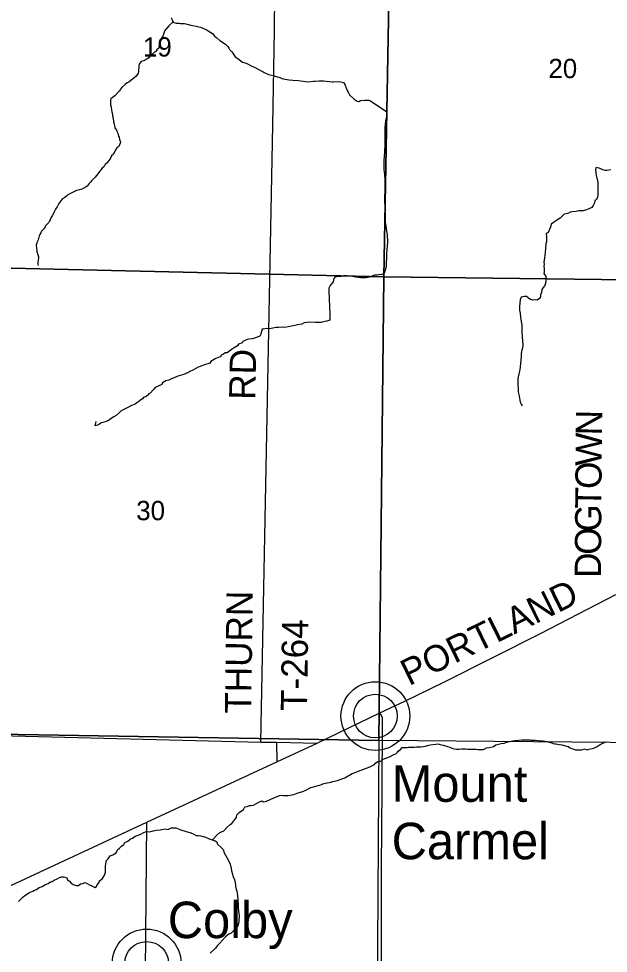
# Model space of a CAD drawing. Extents: x 0 to 34, y 0 to 22.
# Drawn here: x 3.375 to 4.651, y 14.74 to 16.762 of the extents above; entities that cross this region are included whole.
import ezdxf

# ---------------------------------------------------------------- set-up
doc = ezdxf.new("R2010")
doc.units = 0
for name, color, linetype in [('GM_X_County_Road', 7, 'Continuous'), ('GM_X_County_Road_Text', 7, 'Continuous'), ('GM_X_Minor_River', 7, 'Continuous'), ('GM_X_Section', 7, 'Continuous'), ('GM_X_Section_Text', 7, 'Continuous'), ('GM_X_Township_Road', 7, 'Continuous'), ('GM_X_Township_Road_Text', 7, 'Continuous'), ('GM_X_Unincorporated', 7, 'Continuous'), ('GM_X_Unincorporated_Location', 7, 'Continuous'), ('GM_X_Unincorporated_Text', 7, 'Continuous')]:
    doc.layers.add(name, color=color, linetype=linetype)

msp = doc.modelspace()

# ---------------------------------------------------------------- linework, layer by layer
at = {"layer": 'GM_X_County_Road'}
msp.add_lwpolyline([(3.1578, 14.7935), (3.6526, 15.0232), (3.9337, 15.154), (4.0209, 15.1945), (4.1568, 15.2599), (4.2108, 15.2852), (4.2951, 15.3262), (4.5042, 15.4319), (4.6673, 15.5158)], dxfattribs=at)
at = {"layer": 'GM_X_Minor_River'}
for points in [[(3.7106, 16.7555), (3.7092, 16.7553), (3.7, 16.7468), (3.6955, 16.7418), (3.6917, 16.7361), (3.6898, 16.7327), (3.6876, 16.7258), (3.685, 16.7213), (3.6831, 16.716), (3.6823, 16.7133), (3.6812, 16.7099), (3.6805, 16.7053), (3.6786, 16.7015), (3.6782, 16.6985), (3.6741, 16.6943), (3.6718, 16.6912), (3.6692, 16.6897), (3.6654, 16.6859), (3.6605, 16.6828), (3.6571, 16.6775), (3.6533, 16.6752), (3.6488, 16.6721), (3.6457, 16.671)], [(3.7056, 16.7635), (3.7068, 16.7605), (3.7095, 16.7548), (3.7133, 16.7529), (3.7159, 16.7526), (3.7186, 16.7526), (3.7224, 16.7522), (3.7254, 16.7519), (3.7307, 16.7515), (3.7342, 16.7515), (3.7395, 16.75), (3.7475, 16.7482), (3.7589, 16.7459), (3.7649, 16.7445), (3.7687, 16.7433), (3.7805, 16.7388), (3.7832, 16.7369), (3.7908, 16.732), (3.7946, 16.7302), (3.7996, 16.7237), (3.8041, 16.7207), (3.8106, 16.7147), (3.816, 16.7113), (3.8232, 16.706), (3.8274, 16.7018), (3.8301, 16.698), (3.8316, 16.6954), (3.8362, 16.6901)], [(3.8362, 16.6901), (3.8389, 16.6874), (3.8438, 16.6791), (3.8492, 16.6757), (3.8598, 16.6682), (3.8674, 16.6655), (3.8701, 16.664), (3.88, 16.6592), (3.8857, 16.6573), (3.8903, 16.6543), (3.8937, 16.6524), (3.8983, 16.6497), (3.9017, 16.6482), (3.9066, 16.6452), (3.9127, 16.643), (3.9158, 16.6415), (3.9196, 16.6403), (3.926, 16.6389), (3.9348, 16.6362), (3.9378, 16.6351), (3.9473, 16.6317), (3.9564, 16.6306), (3.9606, 16.6299), (3.9686, 16.6292), (3.9804, 16.6285), (3.9853, 16.6277), (3.9959, 16.6263), (4.002, 16.6255), (4.0134, 16.6267), (4.0161, 16.6271), (4.0255, 16.6276), (4.035, 16.6276), (4.0403, 16.6269), (4.0479, 16.6261), (4.0533, 16.6254), (4.0563, 16.6254), (4.0677, 16.6262), (4.0719, 16.6255), (4.0783, 16.6236), (4.0814, 16.6179), (4.0837, 16.6123), (4.0864, 16.6054), (4.0887, 16.6013), (4.0906, 16.5971), (4.1009, 16.5877), (4.1074, 16.5835), (4.1108, 16.5831), (4.115, 16.5847), (4.1244, 16.5859), (4.1286, 16.5859), (4.1324, 16.5855), (4.1351, 16.5852), (4.1709, 16.561), (4.1709, 16.5504), (4.1698, 16.5447), (4.1691, 16.5394), (4.1683, 16.5352), (4.1673, 16.5242), (4.1673, 16.5215), (4.1677, 16.5181), (4.1673, 16.5074), (4.1674, 16.4911), (4.1671, 16.4843), (4.1667, 16.4793), (4.1664, 16.4748), (4.1664, 16.4706), (4.166, 16.4668), (4.1661, 16.463), (4.1653, 16.4573), (4.1654, 16.4451), (4.165, 16.4398), (4.1654, 16.436), (4.1662, 16.4296), (4.1666, 16.4258), (4.1667, 16.4197), (4.167, 16.4166), (4.1671, 16.414), (4.1671, 16.3996), (4.1675, 16.3961), (4.1672, 16.3912), (4.1672, 16.3882), (4.1669, 16.3779), (4.1669, 16.3718), (4.1666, 16.3631), (4.167, 16.3597), (4.167, 16.3498), (4.1674, 16.3437), (4.1678, 16.3392), (4.1679, 16.3274), (4.1683, 16.3209), (4.1687, 16.3175), (4.1699, 16.3092), (4.171, 16.3023), (4.1714, 16.2989), (4.1722, 16.294), (4.1722, 16.2906), (4.173, 16.2826), (4.1731, 16.2761), (4.1727, 16.2716), (4.172, 16.2605), (4.1713, 16.256)], [(3.6457, 16.671), (3.6427, 16.6702), (3.6393, 16.6683), (3.6363, 16.6637), (3.6355, 16.6599), (3.6352, 16.6568), (3.6348, 16.6504), (3.6348, 16.647), (3.6341, 16.6439), (3.6296, 16.6378), (3.6247, 16.6332), (3.6182, 16.6283), (3.6137, 16.6248), (3.6103, 16.6229), (3.6054, 16.6199), (3.5986, 16.6134), (3.5952, 16.6088), (3.5944, 16.6061), (3.5918, 16.6042), (3.5831, 16.5951), (3.5748, 16.5889), (3.574, 16.5859), (3.5741, 16.5756), (3.5753, 16.5703), (3.5764, 16.5646), (3.5768, 16.5601), (3.578, 16.5551), (3.5784, 16.5517), (3.5799, 16.5464), (3.5807, 16.5388), (3.5819, 16.5343), (3.5834, 16.5259), (3.5869, 16.521), (3.5873, 16.5183), (3.5896, 16.5142), (3.5915, 16.5081), (3.5927, 16.5055), (3.5934, 16.5009), (3.5946, 16.4971), (3.5954, 16.4941), (3.592, 16.4857), (3.5878, 16.4823), (3.5841, 16.4765), (3.5803, 16.4686), (3.5762, 16.4651), (3.5747, 16.4617), (3.5728, 16.4583), (3.566, 16.4491), (3.5622, 16.4464), (3.56, 16.4422), (3.5562, 16.4388), (3.5528, 16.4346), (3.5501, 16.4312), (3.5467, 16.4266), (3.5437, 16.4224), (3.5407, 16.4194), (3.5366, 16.4148), (3.5332, 16.4113), (3.5317, 16.4087), (3.5279, 16.4052), (3.5237, 16.3995), (3.5211, 16.3984), (3.515, 16.3945), (3.5116, 16.3934), (3.5067, 16.3915), (3.5002, 16.3899), (3.4946, 16.3872), (3.4862, 16.383), (3.4813, 16.3811), (3.4798, 16.3784), (3.4749, 16.3754), (3.4688, 16.3708), (3.4662, 16.3677), (3.462, 16.3624), (3.4587, 16.3548), (3.4549, 16.3498), (3.453, 16.3452), (3.4515, 16.3422), (3.4481, 16.3357), (3.4451, 16.3312), (3.4432, 16.327), (3.4417, 16.3243), (3.4395, 16.3205), (3.4372, 16.3171), (3.4334, 16.3136), (3.4319, 16.3094), (3.4274, 16.3052), (3.4248, 16.3022), (3.4229, 16.2984), (3.421, 16.2953), (3.4195, 16.2923), (3.4173, 16.2835), (3.415, 16.2793), (3.4146, 16.2763), (3.4135, 16.2717), (3.4136, 16.2657), (3.4143, 16.2611), (3.4147, 16.2577), (3.417, 16.2516), (3.4182, 16.2467), (3.4182, 16.244)], [(4.6559, 16.4346), (4.6479, 16.4338), (4.6437, 16.4337), (4.6388, 16.4349), (4.6308, 16.4382), (4.6243, 16.4401), (4.6232, 16.4352), (4.6236, 16.4283), (4.6248, 16.4234), (4.6279, 16.4082), (4.6283, 16.4033), (4.6284, 16.3805), (4.6277, 16.3759), (4.6251, 16.371), (4.6213, 16.3675), (4.6209, 16.3637), (4.6179, 16.358), (4.6153, 16.3535), (4.6073, 16.35), (4.6035, 16.3485), (4.5963, 16.3465), (4.591, 16.3465), (4.5868, 16.3461), (4.5815, 16.3446), (4.5724, 16.3438), (4.5679, 16.343), (4.563, 16.3407), (4.5554, 16.3387), (4.5463, 16.3303), (4.541, 16.3265), (4.5365, 16.3242), (4.5323, 16.3208), (4.5274, 16.3173), (4.5255, 16.3112), (4.5207, 16.2994), (4.5165, 16.2968), (4.5173, 16.2895), (4.5173, 16.2831), (4.517, 16.2793), (4.5158, 16.2755), (4.5155, 16.2717), (4.5151, 16.2656), (4.514, 16.2557), (4.5126, 16.2447), (4.5115, 16.2352), (4.5119, 16.2306), (4.5115, 16.2268), (4.5119, 16.2204), (4.512, 16.2143), (4.5116, 16.2105), (4.5151, 16.2052), (4.5162, 16.2014), (4.5159, 16.1965), (4.5155, 16.1923), (4.5136, 16.1843), (4.5099, 16.1805), (4.5068, 16.1763), (4.5069, 16.1721), (4.5054, 16.1683), (4.5039, 16.1641), (4.5043, 16.1603), (4.502, 16.1565), (4.4967, 16.1531), (4.4929, 16.1534), (4.4876, 16.153), (4.4811, 16.1549), (4.4735, 16.1606)], [(3.4182, 16.244), (3.4175, 16.2391), (3.4171, 16.2349), (3.4168, 16.2311), (3.4172, 16.2277)], [(4.1713, 16.256), (4.1713, 16.2533), (4.1709, 16.2465), (4.1706, 16.2423), (4.1702, 16.2351), (4.1702, 16.2321), (4.1699, 16.2271), (4.1692, 16.2218), (4.1684, 16.2176), (4.1669, 16.2138), (4.1662, 16.2104), (4.1609, 16.2085), (4.1537, 16.2077), (4.1506, 16.2073), (4.1453, 16.2072), (4.1336, 16.203), (4.1309, 16.2022), (4.1264, 16.2015), (4.1146, 16.2014), (4.1036, 16.2025), (4.0952, 16.2047), (4.085, 16.2058), (4.0781, 16.2054), (4.0732, 16.2042), (4.0698, 16.2038), (4.0664, 16.2038), (4.0633, 16.2034), (4.0592, 16.203), (4.0569, 16.1996), (4.0558, 16.1928), (4.049, 16.1847), (4.0464, 16.1787), (4.0461, 16.1695), (4.0469, 16.1589), (4.0469, 16.1494), (4.0477, 16.1449), (4.0477, 16.1361), (4.0482, 16.1251), (4.0486, 16.1205), (4.0486, 16.1167), (4.0482, 16.1137), (4.0483, 16.1099), (4.0418, 16.1076), (4.0384, 16.1064), (4.0293, 16.1049), (4.0175, 16.1048), (4.0042, 16.1051), (3.9929, 16.1036), (3.9879, 16.1013), (3.9785, 16.0993), (3.9758, 16.0985), (3.9663, 16.0966), (3.958, 16.095), (3.9504, 16.0939), (3.9451, 16.0942), (3.9375, 16.0938), (3.9322, 16.0934), (3.9284, 16.093), (3.925, 16.0922), (3.9216, 16.0918), (3.9182, 16.0911), (3.9155, 16.091), (3.9117, 16.0914), (3.9049, 16.0898), (3.9022, 16.0898), (3.8992, 16.0803), (3.8985, 16.0769), (3.8955, 16.0742), (3.8856, 16.0708), (3.8803, 16.0692), (3.8735, 16.0684), (3.8697, 16.068), (3.8602, 16.0638), (3.8587, 16.0608), (3.8511, 16.0577), (3.8485, 16.0543), (3.8417, 16.0497), (3.8375, 16.0474), (3.8266, 16.0393), (3.822, 16.0386), (3.8186, 16.0363), (3.8133, 16.0336), (3.8118, 16.0305), (3.8069, 16.029), (3.8004, 16.0259), (3.791, 16.0205), (3.7891, 16.0164), (3.7751, 16.0125), (3.7717, 16.0106), (3.7656, 16.0087), (3.7622, 16.0075), (3.7523, 16.0014), (3.7459, 15.9983), (3.7414, 15.996), (3.7372, 15.9941), (3.7345, 15.9926), (3.7198, 15.9883), (3.7118, 15.9848), (3.7088, 15.9841), (3.7001, 15.9798), (3.6936, 15.9783)], [(4.4735, 16.1606), (4.4697, 16.1605), (4.4625, 16.1594), (4.4603, 16.1533), (4.4584, 16.1396), (4.4589, 16.1312), (4.46, 16.1248), (4.4608, 16.1157), (4.4616, 16.1111), (4.4636, 16.0986), (4.4637, 16.0838), (4.4645, 16.0739), (4.4661, 16.0553), (4.465, 16.0492), (4.4635, 16.0447), (4.4624, 16.0374), (4.462, 16.0306), (4.4595, 16.0025), (4.4569, 15.9933), (4.4551, 15.9835), (4.4551, 15.977), (4.4556, 15.9553), (4.4567, 15.9508), (4.4579, 15.9455), (4.4587, 15.9409), (4.4602, 15.9322), (4.4622, 15.928), (4.4645, 15.9242)], [(3.6936, 15.9783), (3.6864, 15.9741), (3.6849, 15.9707), (3.6705, 15.9638), (3.6671, 15.9596), (3.6596, 15.9519), (3.6569, 15.9504), (3.6547, 15.9473), (3.6501, 15.9439), (3.646, 15.9427), (3.6429, 15.9397), (3.6399, 15.937), (3.6343, 15.9328), (3.6316, 15.9317), (3.6274, 15.9278), (3.6191, 15.9251), (3.6127, 15.9217), (3.604, 15.9167), (3.5972, 15.9133), (3.5934, 15.9098), (3.5862, 15.9033), (3.5809, 15.9006), (3.5775, 15.8983), (3.5748, 15.8964), (3.5718, 15.8941), (3.568, 15.8915), (3.5623, 15.8895), (3.5574, 15.888), (3.5536, 15.8876), (3.5498, 15.8845), (3.5461, 15.8826), (3.5411, 15.8807), (3.543, 15.8902)], [(3.7942, 14.9848), (3.796, 14.9866), (3.8036, 14.9953), (3.8105, 15.0013), (3.8189, 15.0047), (3.8262, 15.0126), (3.833, 15.0182), (3.8361, 15.0208), (3.843, 15.0295), (3.8464, 15.0336), (3.8469, 15.039), (3.8522, 15.0446), (3.8614, 15.0506), (3.8645, 15.0563), (3.8698, 15.0574), (3.8747, 15.0596), (3.8778, 15.0596), (3.8831, 15.0603), (3.8937, 15.0659), (3.901, 15.0692), (3.9051, 15.0677), (3.9085, 15.068), (3.9112, 15.0688), (3.9207, 15.0732), (3.9306, 15.0773), (3.9394, 15.081), (3.9428, 15.0818), (3.9473, 15.0814), (3.9504, 15.081), (3.9542, 15.0809), (3.9583, 15.0813), (3.9705, 15.0834), (3.9777, 15.0864), (3.9823, 15.0875), (3.9899, 15.0897), (3.9967, 15.0923), (4.0074, 15.0983), (4.0131, 15.1001), (4.0184, 15.1016), (4.0234, 15.1027), (4.0268, 15.1034), (4.0302, 15.1049), (4.0332, 15.106), (4.0363, 15.1072), (4.0389, 15.1079), (4.0427, 15.1086), (4.0473, 15.109), (4.0507, 15.1101), (4.0549, 15.1112), (4.0648, 15.1137), (4.0705, 15.1156), (4.0747, 15.1171), (4.0808, 15.1193), (4.0964, 15.1286), (4.1032, 15.1309), (4.1135, 15.1353), (4.1181, 15.1368), (4.1268, 15.1405), (4.1299, 15.1409), (4.1375, 15.1446), (4.1447, 15.1483), (4.1474, 15.151), (4.1523, 15.1547), (4.1577, 15.1551), (4.1607, 15.1569), (4.1638, 15.1596), (4.1771, 15.1651), (4.187, 15.1696), (4.1915, 15.1711), (4.1946, 15.1745), (4.1965, 15.1771), (4.2011, 15.1805), (4.2049, 15.1846), (4.2118, 15.1853), (4.2159, 15.1853), (4.2186, 15.1857), (4.2231, 15.1856), (4.2315, 15.1859), (4.236, 15.1863), (4.2429, 15.1862), (4.2455, 15.1866), (4.255, 15.188), (4.26, 15.1891), (4.2657, 15.1906), (4.2778, 15.1923), (4.282, 15.1927), (4.2846, 15.1923), (4.2873, 15.1915), (4.2933, 15.1903), (4.3032, 15.1872), (4.3077, 15.186), (4.3111, 15.1845), (4.3141, 15.1829), (4.3225, 15.1813), (4.3285, 15.1813), (4.3335, 15.182), (4.3418, 15.1819), (4.3464, 15.1815), (4.3498, 15.1815), (4.36, 15.1817), (4.3642, 15.1817)], [(4.3642, 15.1817), (4.3687, 15.1809), (4.3733, 15.1805), (4.3767, 15.1805), (4.3809, 15.1808), (4.3873, 15.1842), (4.3927, 15.1853), (4.3995, 15.1863), (4.4021, 15.1871), (4.4075, 15.1908), (4.4189, 15.1934), (4.4253, 15.1945), (4.4333, 15.197), (4.4367, 15.1978), (4.4436, 15.1992), (4.4485, 15.2), (4.4546, 15.2003), (4.4573, 15.2006), (4.4637, 15.2017), (4.4701, 15.2013), (4.4808, 15.2012), (4.4834, 15.2008), (4.4925, 15.2007), (4.4993, 15.2003), (4.5096, 15.1994), (4.5183, 15.1978), (4.5228, 15.1963), (4.5258, 15.1955), (4.5285, 15.1947), (4.5315, 15.1935), (4.5349, 15.1931), (4.5376, 15.1927), (4.5448, 15.1911), (4.5501, 15.1907), (4.5607, 15.1876), (4.5637, 15.1868), (4.5671, 15.1849), (4.5697, 15.1837), (4.5735, 15.1821), (4.5762, 15.1814), (4.58, 15.1802), (4.5837, 15.1798), (4.5868, 15.1801), (4.5925, 15.1801), (4.5959, 15.1808), (4.5993, 15.1819), (4.6031, 15.1804), (4.6057, 15.1796), (4.6084, 15.1811), (4.6168, 15.1829), (4.6209, 15.1844), (4.627, 15.1874), (4.6328, 15.1911), (4.6377, 15.1937), (4.6438, 15.1963), (4.6465, 15.1974)], [(3.4758, 14.9041), (3.4796, 14.9026), (3.4808, 14.8988), (3.4854, 14.8958), (3.4892, 14.8913), (3.493, 14.8882), (3.4995, 14.886), (3.5044, 14.8864), (3.5089, 14.8898), (3.5135, 14.891), (3.5195, 14.8929), (3.5233, 14.8907), (3.5287, 14.8876), (3.5336, 14.8858), (3.5397, 14.882), (3.5435, 14.8839), (3.5454, 14.8877), (3.5491, 14.8927), (3.5503, 14.8965), (3.5567, 14.9018), (3.5601, 14.9076), (3.5631, 14.9148), (3.563, 14.9292), (3.5641, 14.933), (3.5656, 14.9402), (3.569, 14.9441), (3.5735, 14.9509), (3.5792, 14.9528), (3.586, 14.9567), (3.5894, 14.9635), (3.5932, 14.967), (3.5977, 14.9712), (3.6026, 14.9754), (3.6049, 14.9792), (3.6113, 14.9823), (3.6162, 14.9868), (3.6212, 14.9891), (3.6272, 14.993), (3.6314, 14.9949), (3.6397, 14.9976), (3.6446, 15.0003), (3.6511, 15.003), (3.6591, 15.0022), (3.6659, 15.0049), (3.6731, 15.0061), (3.6814, 15.0065), (3.692, 15.0092), (3.6977, 15.0077), (3.7061, 15.0112), (3.7103, 15.0108), (3.7156, 15.0112), (3.7258, 15.0071), (3.7376, 15.003), (3.7464, 15.0008), (3.7544, 14.9974), (3.7593, 14.9947), (3.7642, 14.9944), (3.7696, 14.994), (3.7741, 14.9925), (3.7779, 14.9914), (3.7874, 14.9873), (3.7935, 14.985), (3.8, 14.9832), (3.8038, 14.9809), (3.8053, 14.976), (3.8118, 14.9703), (3.8179, 14.9642), (3.8198, 14.957), (3.8256, 14.9472), (3.8302, 14.9389), (3.8329, 14.9324), (3.8352, 14.9229), (3.836, 14.9184), (3.8379, 14.9108), (3.8387, 14.9066), (3.8414, 14.9013), (3.8429, 14.8964), (3.8441, 14.8888), (3.8445, 14.885), (3.8461, 14.8785), (3.8472, 14.874), (3.848, 14.8698), (3.8488, 14.8641), (3.8496, 14.8546), (3.8504, 14.8447), (3.8504, 14.8394), (3.8509, 14.8307), (3.8516, 14.8261), (3.852, 14.8212), (3.8521, 14.817), (3.8517, 14.8132), (3.8517, 14.809), (3.851, 14.8041), (3.8491, 14.7988), (3.845, 14.7923), (3.8389, 14.7866), (3.8351, 14.7835), (3.8302, 14.7808), (3.823, 14.7755), (3.8159, 14.7682), (3.8098, 14.761)], [(3.3751, 14.852), (3.3849, 14.8615), (3.3887, 14.8649), (3.3989, 14.8711), (3.4058, 14.8741), (3.4099, 14.8761), (3.4137, 14.8776), (3.4194, 14.8822), (3.4258, 14.8845), (3.433, 14.8887), (3.4391, 14.8906), (3.444, 14.8941), (3.4478, 14.8949), (3.4523, 14.8979), (3.4584, 14.901), (3.4637, 14.904), (3.4682, 14.9052), (3.472, 14.9052), (3.4758, 14.9041)], [(3.8098, 14.761), (3.8045, 14.756), (3.8008, 14.7511), (3.7894, 14.7396)]]:
    msp.add_lwpolyline(points, dxfattribs=at)
at = {"layer": 'GM_X_Section'}
for points in [[(3.1868, 17.2222), (4.1831, 17.1984), (4.1651, 16.2036), (3.1722, 16.2262)], [(4.1831, 17.1984), (5.1818, 17.1932), (5.166, 16.1912), (4.1651, 16.2036)], [(4.1651, 16.2036), (4.1541, 15.2001), (3.1571, 15.217), (3.1722, 16.2262)], [(4.1651, 16.2036), (5.166, 16.1912), (5.1562, 15.1911), (4.1541, 15.2001)], [(3.1571, 15.217), (4.1541, 15.2001), (4.1481, 14.2013), (3.1458, 14.2165)]]:
    msp.add_lwpolyline(points, close=True, dxfattribs=at)
at = {"layer": 'GM_X_Township_Road'}
for p, q in [((3.933, 15.1962), (3.9337, 15.154)), ((3.6496, 14.6996), (3.6526, 15.0232))]:
    msp.add_line(p, q, dxfattribs=at)
for points in [[(3.8988, 15.1968), (3.9249, 16.5318), (3.9284, 16.7361), (3.9302, 16.8958), (3.9305, 17.0084), (3.9315, 17.1247), (3.9321, 17.2011), (3.9315, 17.213)], [(4.1594, 14.2029), (4.1598, 14.9242), (4.1615, 15.0983), (4.1626, 15.2315), (4.1623, 15.2495), (4.1604, 15.2545), (4.1568, 15.2599)], [(3.163, 15.2153), (3.8988, 15.1968), (3.933, 15.1962), (4.0209, 15.1945)]]:
    msp.add_lwpolyline(points, dxfattribs=at)
at = {"layer": 'GM_X_Unincorporated'}
for centre, radius in [((4.1469, 15.253), 0.0744), ((4.1469, 15.253), 0.0472), ((3.6522, 14.7178), 0.0744), ((3.6522, 14.7178), 0.0472)]:
    msp.add_circle(centre, radius, dxfattribs=at)
at = {"layer": 'GM_X_Unincorporated_Location'}
msp.add_line((4.1469, 15.253), (4.1469, 15.253), dxfattribs=at)

# ---------------------------------------------------------------- texts
at = {"layer": 'GM_X_County_Road_Text'}
msp.add_text('PORTLAND', height=0.05682, rotation=26.1616, dxfattribs=at).set_placement((4.2197, 15.3175))
at = {"layer": 'GM_X_Section_Text'}
for s, p in [('19', (3.6442, 16.68)), ('20', (4.5212, 16.6333)), ('30', (3.6296, 15.6767))]:
    msp.add_text(s, height=0.04186, rotation=0, dxfattribs=at).set_placement(p)
at = {"layer": 'GM_X_Township_Road_Text'}
for s, height, rotation, p in [('RD', 0.05682, 89.0109, (3.8872, 15.937)), ('N', 0.0568, 88.8124, (4.637, 15.8599)), ('W', 0.0568, 89.5712, (4.6365, 15.7943)), ('O', 0.0568, 89.5861, (4.6361, 15.7443)), ('T', 0.0568, 89.58, (4.6358, 15.7018)), ('G', 0.0568, 89.5851, (4.6355, 15.6518)), ('O', 0.0568, 89.5811, (4.6351, 15.6018)), ('D', 0.0568, 89.5847, (4.6347, 15.5518)), ('THURN', 0.05682, 89.2019, (3.8781, 15.2578)), ('T-264', 0.05682, 89.1579, (3.999, 15.2635))]:
    msp.add_text(s, height=height, rotation=rotation, dxfattribs=at).set_placement(p)
at = {"layer": 'GM_X_Unincorporated_Text'}
for s, p in [('Mount', (4.1821, 15.0674)), ('Carmel', (4.1821, 14.9432)), ('Colby', (3.6979, 14.7724))]:
    msp.add_text(s, height=0.07898, rotation=0, dxfattribs=at).set_placement(p)

doc.saveas('drawing.dxf')
